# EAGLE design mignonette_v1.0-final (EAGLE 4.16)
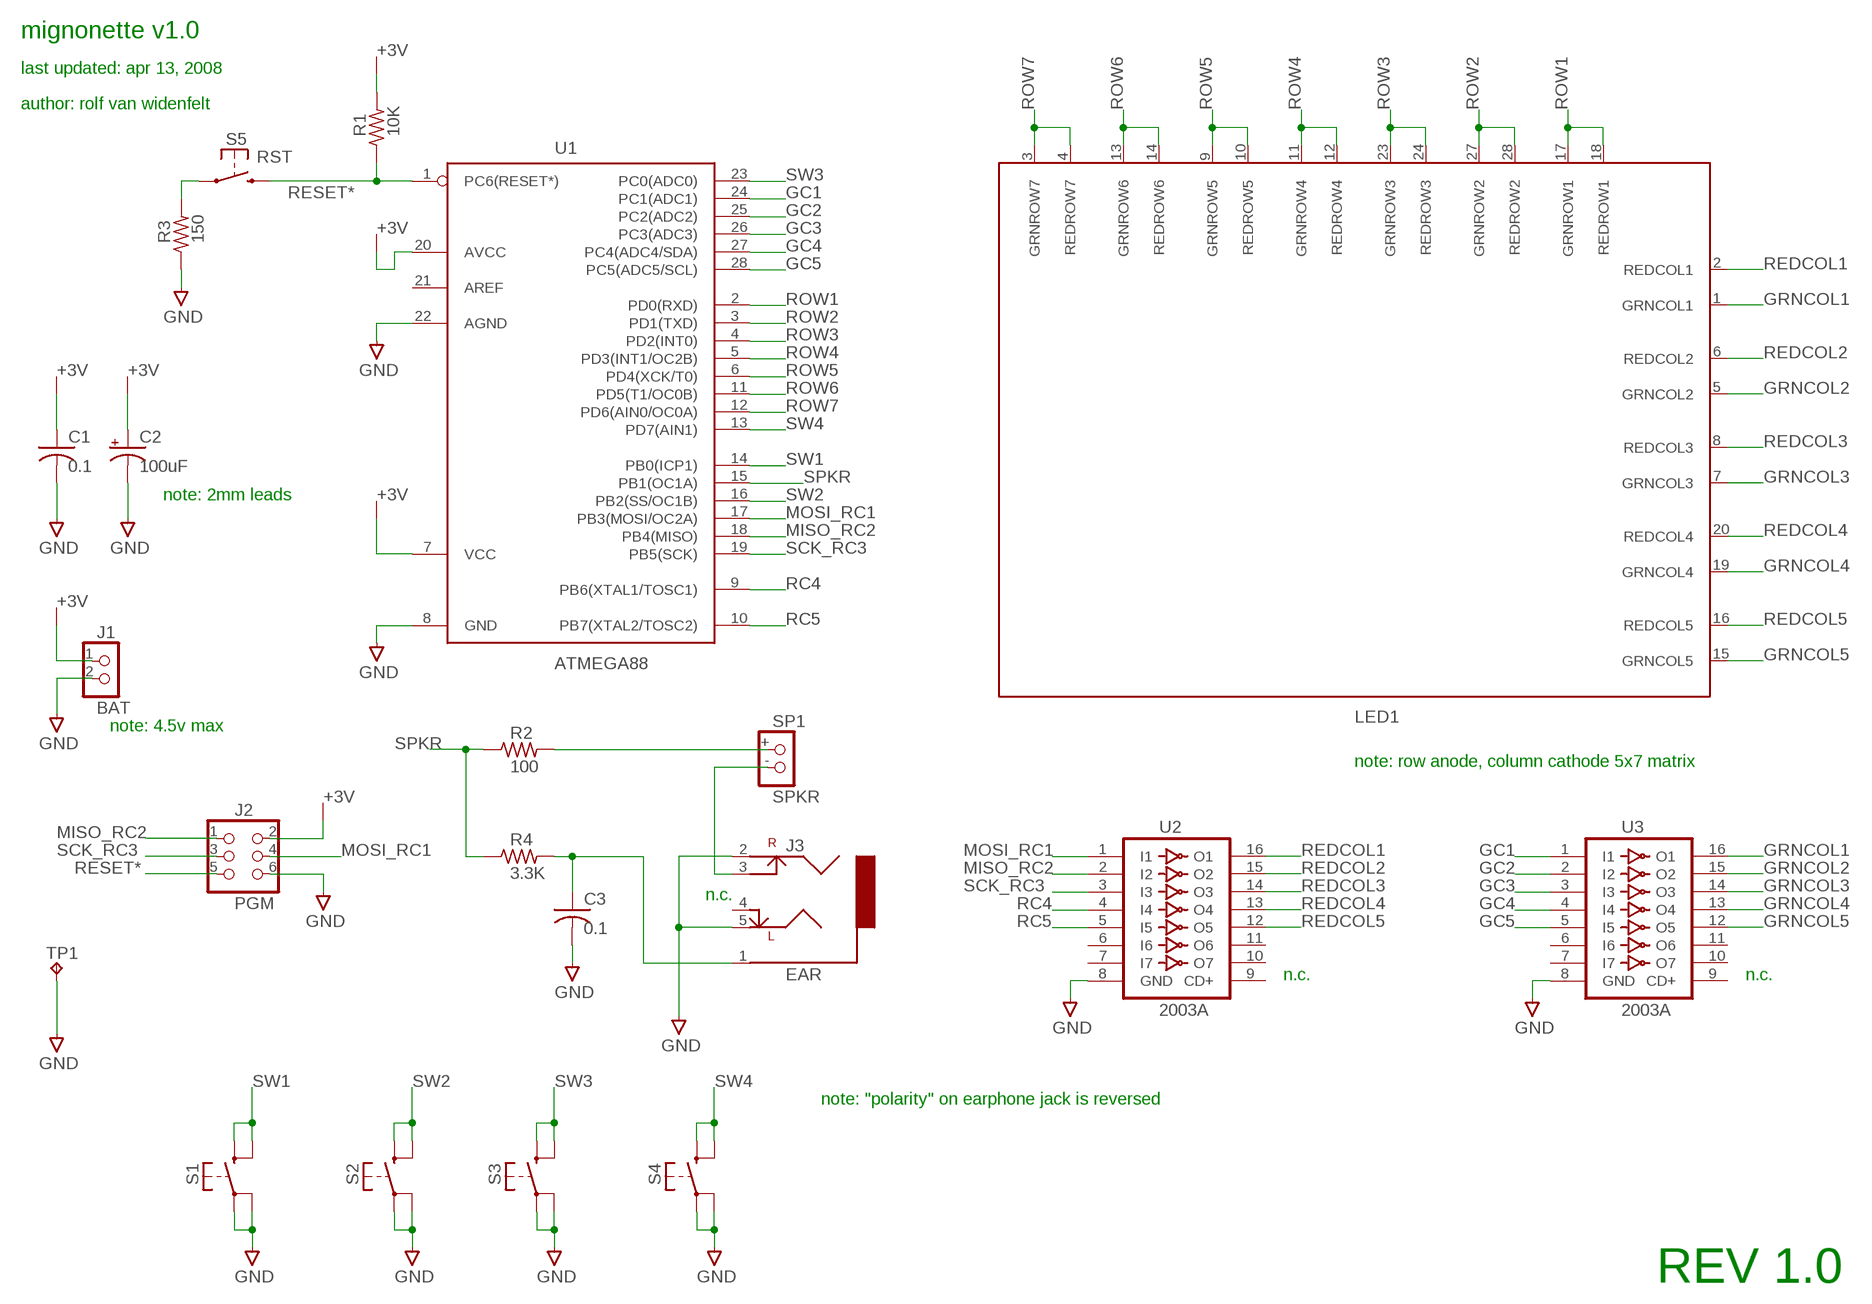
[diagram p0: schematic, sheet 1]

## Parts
C1  0.1  CAPACITORCAP100_FATPAD  [CAP100_FATPAD]
C2  100uF  CAPACITOR_POLPOLCAP2.0MM_FATPAD  [POLCAP2.0MM_FATPAD]
C3  0.1  CAPACITORCAP100_FATPAD  [CAP100_FATPAD]
J1  BAT  HEADER_1X2HEADER_1X2  [HEADER_1X2]
J2  PGM  HEADER_2X3HEADER_2X3  [HEADER_2X3]
J3  EAR  AUDIOJACK-SWITCHEDSTX-3081  [KYCON-STX-3081]
LED1  BICOLOR_5X7BICOLOR_28PIN  [BICOLOR_28PIN]
R1  10K  RESISTORRES350_FATPAD  [RES350_FATPAD]
R2  100  RESISTORRES350_FATPAD  [RES350_FATPAD]
R3  150  RESISTORRES350_FATPAD  [RES350_FATPAD]
R4  3.3K  RESISTORRES350_FATPAD  [RES350_FATPAD]
S1  TACTILE_SWITCH_SPSTB3F-1000-EASY  [B3F-1000-EASY]
S2  TACTILE_SWITCH_SPSTB3F-1000-EASY  [B3F-1000-EASY]
S3  TACTILE_SWITCH_SPSTB3F-1000-EASY-MIR  [B3F-1000-EASY-MIR]
S4  TACTILE_SWITCH_SPSTB3F-1000-EASY-MIR  [B3F-1000-EASY-MIR]
S5  RST  TACTILE_SPST  [TACTILE_SPST]
SP1  SPKR  BUZZERBUZZER_12MM  [BUZZER_12MM]
TP1  TESTPOINTTP_029  [TP_029]
U1  ATMEGA88  MEGAXX8DIL28-3  [DIL28-3]
U2  2003A  ULN2003AN  [DIL16]
U3  2003A  ULN2003AN  [DIL16]

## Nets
+3V: C1.1 C2.+ J1.1 J2.2 R1.2 U1.7(VCC) U1.20(AVCC)
EAROUT: C3.1 J3.1 R4.2
EARSW: J3.3 SP1.-
GC1: U1.24(PC1(ADC1)) U3.1(I1)
GC2: U1.25(PC2(ADC2)) U3.2(I2)
GC3: U1.26(PC3(ADC3)) U3.3(I3)
GC4: U1.27(PC4(ADC4/SDA)) U3.4(I4)
GC5: U1.28(PC5(ADC5/SCL)) U3.5(I5)
GND: C1.2 C2.- C3.2 J1.2 J2.6 J3.2 J3.5 R3.1 S1.P$1 S1.P$2 S2.P$1 S2.P$2 S3.P$1 S3.P$2 S4.P$1 S4.P$2 TP1.P$1(TP) U1.8(GND) U1.22(AGND) U2.8(GND) U3.8(GND)
GRNCOL1: LED1.1(GRNCOL1) U3.16(O1)
GRNCOL2: LED1.5(GRNCOL2) U3.15(O2)
GRNCOL3: LED1.7(GRNCOL3) U3.14(O3)
GRNCOL4: LED1.19(GRNCOL4) U3.13(O4)
GRNCOL5: LED1.15(GRNCOL5) U3.12(O5)
MISO_RC2: J2.1 U1.18(PB4(MISO)) U2.2(I2)
MOSI_RC1: J2.4 U1.17(PB3(MOSI/OC2A)) U2.1(I1)
N$2: R3.2 S5.P$1
N$3: R2.2 SP1.+
RC4: U1.9(PB6(XTAL1/TOSC1)) U2.4(I4)
RC5: U1.10(PB7(XTAL2/TOSC2)) U2.5(I5)
REDCOL1: LED1.2(REDCOL1) U2.16(O1)
REDCOL2: LED1.6(REDCOL2) U2.15(O2)
REDCOL3: LED1.8(REDCOL3) U2.14(O3)
REDCOL4: LED1.20(REDCOL4) U2.13(O4)
REDCOL5: LED1.16(REDCOL5) U2.12(O5)
RESET*: J2.5 R1.1 S5.P$2 U1.1(PC6(RESET*))
ROW1: LED1.17(GRNROW1) LED1.18(REDROW1) U1.2(PD0(RXD))
ROW2: LED1.27(GRNROW2) LED1.28(REDROW2) U1.3(PD1(TXD))
ROW3: LED1.23(GRNROW3) LED1.24(REDROW3) U1.4(PD2(INT0))
ROW4: LED1.11(GRNROW4) LED1.12(REDROW4) U1.5(PD3(INT1/OC2B))
ROW5: LED1.9(GRNROW5) LED1.10(REDROW5) U1.6(PD4(XCK/T0))
ROW6: LED1.13(GRNROW6) LED1.14(REDROW6) U1.11(PD5(T1/OC0B))
ROW7: LED1.3(GRNROW7) LED1.4(REDROW7) U1.12(PD6(AIN0/OC0A))
SCK_RC3: J2.3 U1.19(PB5(SCK)) U2.3(I3)
SPKR: R2.1 R4.1 U1.15(PB1(OC1A))
SW1: S1.P$3 S1.P$4 U1.14(PB0(ICP1))
SW2: S2.P$3 S2.P$4 U1.16(PB2(SS/OC1B))
SW3: S3.P$3 S3.P$4 U1.23(PC0(ADC0))
SW4: S4.P$3 S4.P$4 U1.13(PD7(AIN1))
Unconnected: J3.4 U1.21(AREF) U2.6(I6) U2.7(I7) U2.9(CD+) U2.10(O7) U2.11(O6) U3.6(I6) U3.7(I7) U3.9(CD+) U3.10(O7) U3.11(O6)

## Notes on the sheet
- mignonette v1.0
- last updated: apr 13, 2008
- author: rolf van widenfelt
- note: 2mm leads
- note: 4.5v max
- note: row anode, column cathode 5x7 matrix
- n.c.
- n.c. | n.c.
- note: "polarity" on earphone jack is reversed
- REV 1.0

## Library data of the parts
C1 C3 = basic:CAPACITOR
C2 = basic:CAPACITOR_POL
J1 = header-extras:HEADER_1X2
J2 = header-extras:HEADER_2X3
J3 = audiojack-kycon:AUDIOJACK-SWITCHED
LED1 = led5x7-bicolor:BICOLOR_5X7
R1-R4 = basic:RESISTOR: RESISTOR
S1-S4 = switch-omron-B3F:TACTILE_SWITCH_SPST
S5 = jameco-switches:TACTILE_SPST
SP1 = buzzer-pcmount:BUZZER
TP1 = testpoints:TESTPOINT
U1 = atmel-megaXX8-dip:MEGAXX8
U2 U3 = uln2003a:ULN2003A: DRIVER ARRAY

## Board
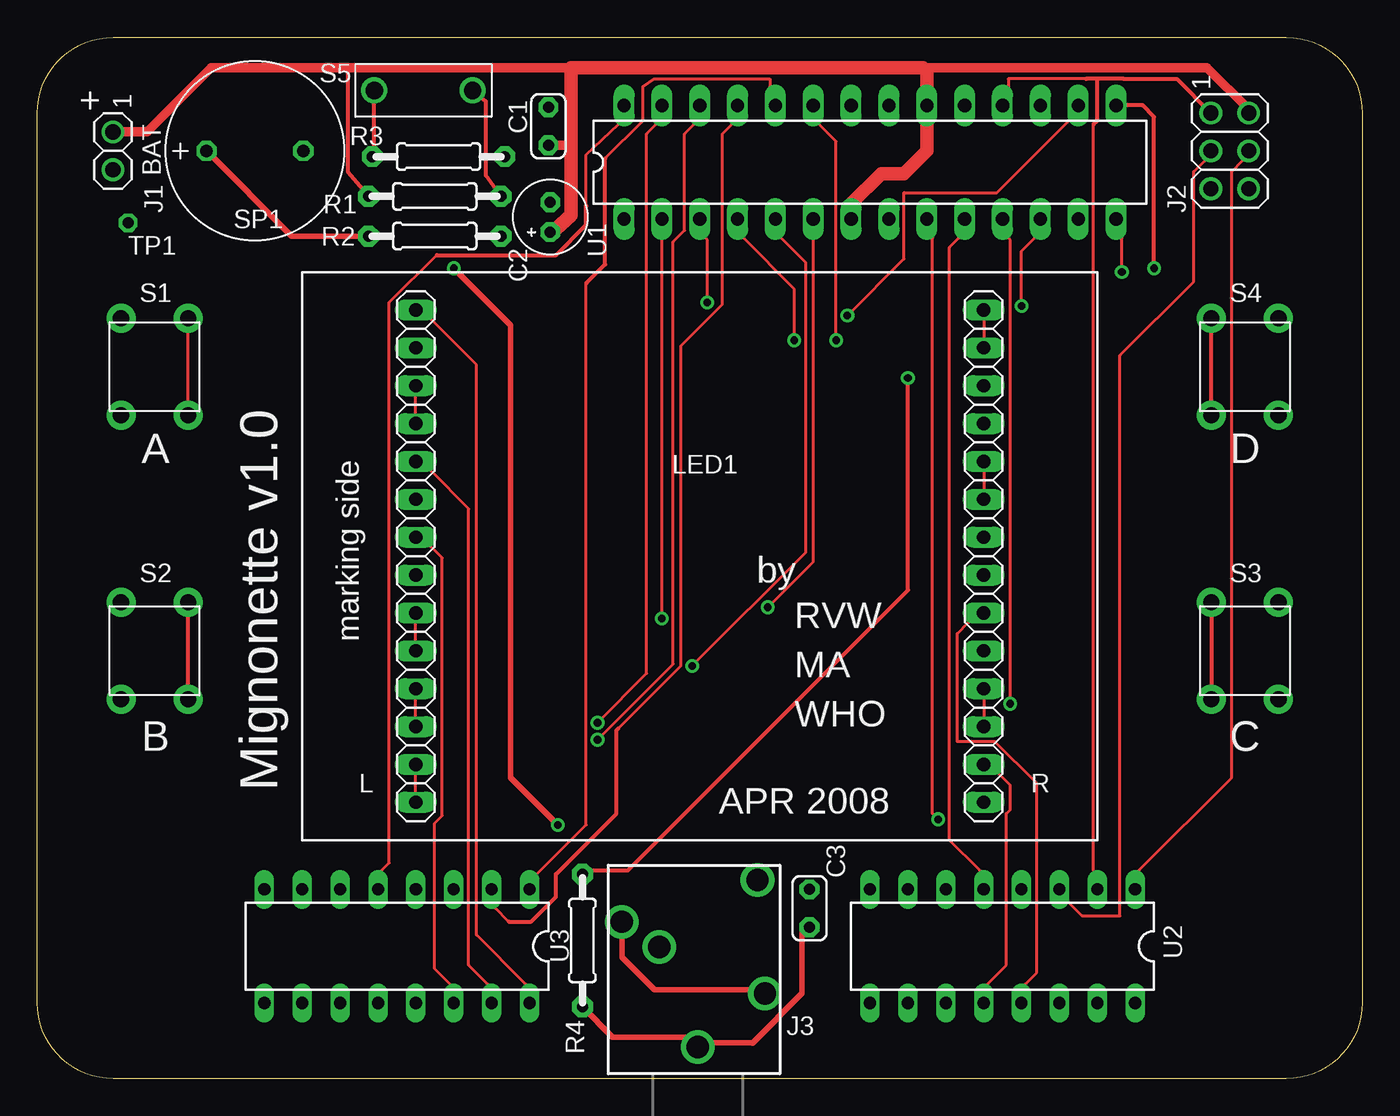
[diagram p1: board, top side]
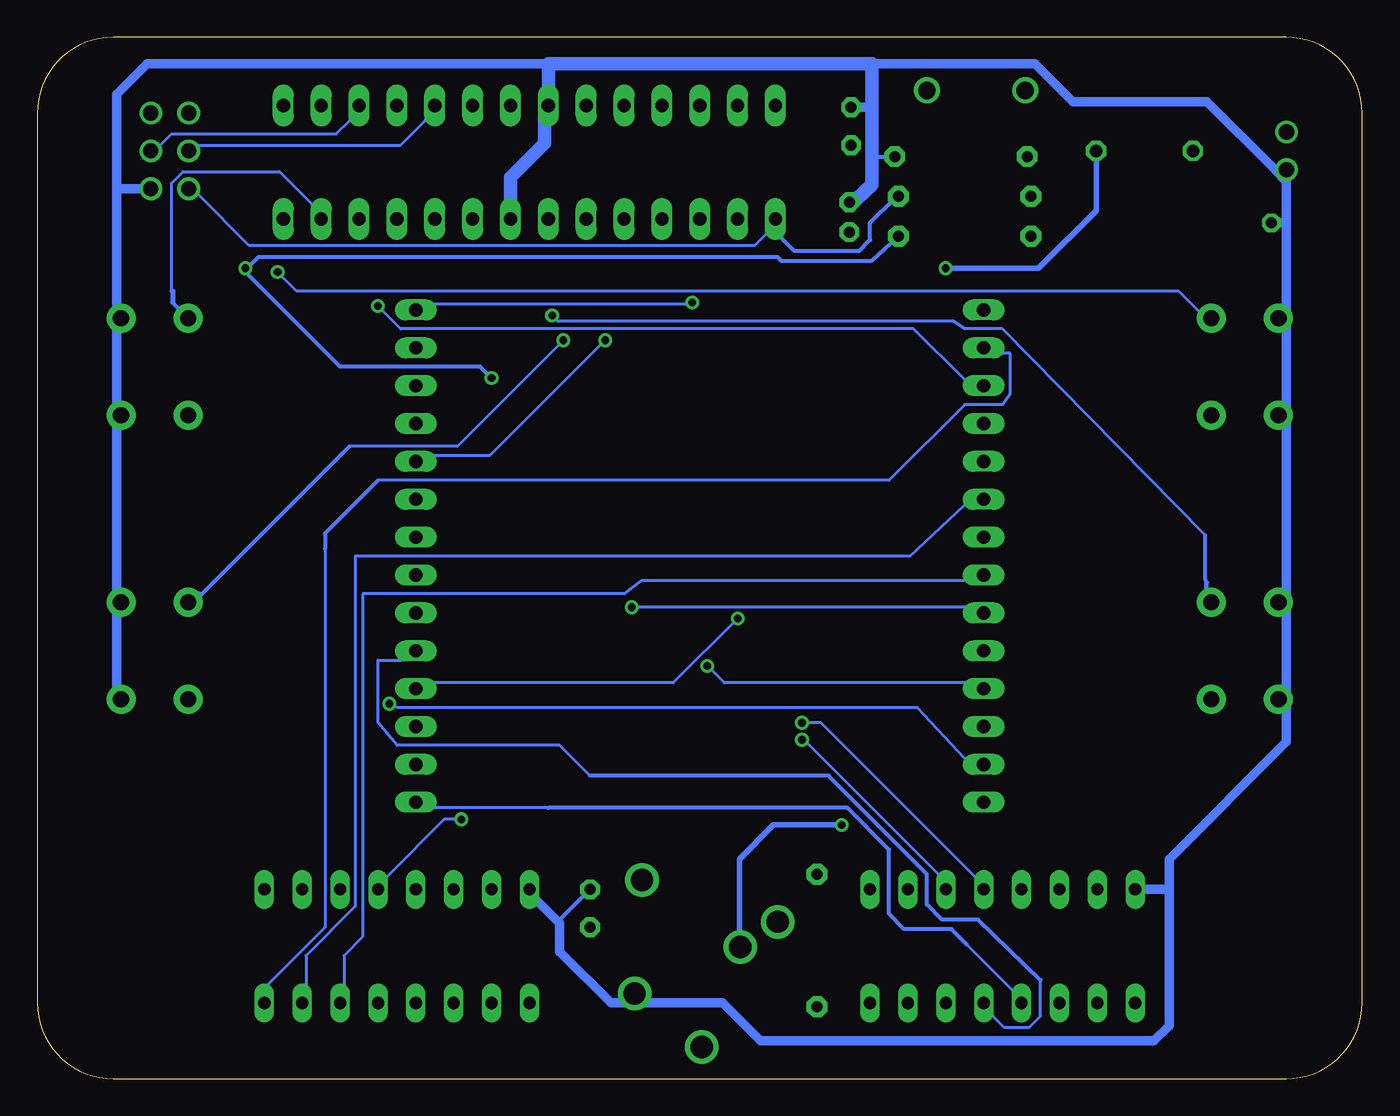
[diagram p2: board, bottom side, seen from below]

Size 88.9 x 69.85 mm. Coordinates in mm from the lower left corner, seen from the top.
Outline: 0,5.08 0,64.77 arc-90 5.08,69.85 83.82,69.85 arc-90 88.9,64.77 88.9,5.08 arc-90 83.82,0 5.08,0 arc-90 0,5.08
Copper layers (1*16): Top 0.035mm / dielectric 1.5mm / Bottom 0.035mm
Design rules "drc8mil10mil": minimum track width 8mil, minimum drill 20mil, track to track 8mil, track to pad 8mil, pad to pad 8mil, via to via 8mil, smd to smd 8mil, copper to edge 20mil, drill to drill 10mil, minimum pad ring 10mil, minimum via ring 8mil, stop-mask expansion 4mil, vias tented up to drill 0mil, thermal gap 10mil

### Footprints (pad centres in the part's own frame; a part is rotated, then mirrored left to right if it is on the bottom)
CAP100_FATPAD = drill 0.737 pad 1.321 octagon: 1 -1.27,0; 2 1.27,0
POLCAP2.0MM_FATPAD = drill 0.737 pad 1.321 octagon: + -1,0; - 1,0
HEADER_1X2 = drill 1.016 round: 1 -1.27,0; 2 1.27,0
HEADER_2X3 = drill 1.016 round: 1 -2.54,-1.27; 2 -2.54,1.27; 3 0,-1.27; 4 0,1.27; 5 2.54,-1.27; 6 2.54,1.27
KYCON-STX-3081 = drill 1.5 round: 1 -5.3,0; 2 -13.7,-5.1; 3 -12,-2.6; 4 -16.5,4; 5 -8.9,4.5
BICOLOR_28PIN = drill 0.889 long: 1 -19.05,16.51; 2 -19.05,13.97; 3 -19.05,11.43; 4 -19.05,8.89; 5 -19.05,6.35; 6 -19.05,3.81; 7 -19.05,1.27; 8 -19.05,-1.27; 9 -19.05,-3.81; 10 -19.05,-6.35; 11 -19.05,-8.89; 12 -19.05,-11.43; 13 -19.05,-13.97; 14 -19.05,-16.51; 15 19.05,-16.51; 16 19.05,-13.97; 17 19.05,-11.43; 18 19.05,-8.89; 19 19.05,-6.35; 20 19.05,-3.81; 21 19.05,-1.27; 22 19.05,1.27; 23 19.05,3.81; 24 19.05,6.35; 25 19.05,8.89; 26 19.05,11.43; 27 19.05,13.97; 28 19.05,16.51
RES350_FATPAD = drill 0.737 pad 1.397 octagon: 1 -4.445,0; 2 4.445,0
B3F-1000-EASY = drill 1.092 pad 1.93 round: P$1 -2.25,-3.25; P$2 -2.25,3.25; P$3 2.25,-3.25; P$4 2.25,3.25
B3F-1000-EASY-MIR = drill 1.092 pad 1.93 round: P$1 2.25,-3.25; P$2 2.25,3.25; P$3 -2.25,-3.25; P$4 -2.25,3.25
TACTILE_SPST = drill 1.168 round: P$1 0,0; P$2 0,6.604
BUZZER_12MM = drill 0.838 octagon: + -3.25,0; - 3.25,0
TP_029 = drill 0.737 octagon: P$1 0,0
DIL28-3 = drill 0.889 long: 1 -16.51,-3.81; 2 -13.97,-3.81; 3 -11.43,-3.81; 4 -8.89,-3.81; 5 -6.35,-3.81; 6 -3.81,-3.81; 7 -1.27,-3.81; 8 1.27,-3.81; 9 3.81,-3.81; 10 6.35,-3.81; 11 8.89,-3.81; 12 11.43,-3.81; 13 13.97,-3.81; 14 16.51,-3.81; 15 16.51,3.81; 16 13.97,3.81; 17 11.43,3.81; 18 8.89,3.81; 19 6.35,3.81; 20 3.81,3.81; 21 1.27,3.81; 22 -1.27,3.81; 23 -3.81,3.81; 24 -6.35,3.81; 25 -8.89,3.81; 26 -11.43,3.81; 27 -13.97,3.81; 28 -16.51,3.81
DIL16 = drill 0.813 long: 1 -8.89,-3.81; 2 -6.35,-3.81; 3 -3.81,-3.81; 4 -1.27,-3.81; 5 1.27,-3.81; 6 3.81,-3.81; 7 6.35,-3.81; 8 8.89,-3.81; 9 8.89,3.81; 10 6.35,3.81; 11 3.81,3.81; 12 1.27,3.81; 13 -1.27,3.81; 14 -3.81,3.81; 15 -6.35,3.81; 16 -8.89,3.81

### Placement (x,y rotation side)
C1  34.29,63.88 90 top
C2  34.42,57.78 90 top
C3  51.82,11.43 90 top
J1  5.08,62.23 270 top
J2  80.01,62.23 270 top
J3  44.32,-3.17 270 top
LED1  44.45,35.05 0 top
R1  26.67,59.18 180 top
R2  26.67,56.52 180 top
R3  26.92,61.85 180 top
R4  36.58,9.27 270 top
S1  7.87,47.75 0 top
S2  7.87,28.7 0 top
S3  81.03,28.7 0 top
S4  81.03,47.75 0 top
S5  22.61,66.29 270 top
SP1  14.61,62.23 0 top
TP1  6.1,57.4 0 top
U1  55.88,61.47 0 top
U2  64.77,8.89 180 top
U3  24.13,8.89 180 top

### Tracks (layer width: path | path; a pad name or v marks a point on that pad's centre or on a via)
+3V
  Top 0.254: R1.2 20.83,60.83 20.83,67.82
  Top 0.635: J2.2 81.28,65.02 78.49,67.82 59.44,67.82 59.69,67.56 | 35.81,67.82 20.83,67.82 11.68,67.82 7.37,63.5 J1.1 4.83,63.5 | 54.61,58.67 U1.7 | 34.42,56.64 C2.+ | 35.81,62.61 C1.1
  Top 0.889: 59.44,67.82 35.81,67.82 35.81,62.61 35.81,57.91 34.42,56.64 | 59.69,67.56 U1.20 59.69,62.23 58.17,60.71 56.64,60.71 54.61,58.67
EAROUT
  Top 0.254: 51.69,10.16 C3.1 | J3.1 44.32,2.16 44.32,2.41 | 47.94,2.41 47.97,2.38
  Top 0.381: R4.2 38.61,2.79 43.56,2.79 43.94,2.41 44.32,2.41 47.94,2.41 | 47.97,2.38 51.31,5.71 51.31,9.78 51.69,10.16
EARSW  (via drill 0.51)
  Top 0.381: v27.94,54.36 31.75,50.55 31.75,20.19 v34.92,17.02
  Bottom 0.254: 41.72,9.08 41.66,9.02 | J3.3 41.72,9.08 | 41.72,9.08 41.78,9.14
  Bottom 0.381: SP1.- 17.86,58.22 21.72,54.36 v27.94,54.36 | v34.92,17.02 39.5,17.02 41.78,14.73 41.78,9.14
GC1
  Top 0.203: 36.83,53.34 36.83,17.02 33.27,13.46 U3.1 | 38.1,61.72 40.64,64.26 40.64,66.55 41.4,67.06 49.15,67.06 49.15,66.55 U1.24
  Top 0.254: 38.1,61.72 38.1,54.61 36.83,53.34
GC2
  Top 0.203: 31.62,10.54 30.73,11.43 U3.2 | 38.99,23.5 43.18,27.69 43.18,49.15 45.97,51.94 45.97,63.37 46.61,64.01 U1.25
  Top 0.254: 31.62,10.54 33.15,10.54 34.8,12.19 34.8,13.72 38.86,17.78 38.86,23.37 38.99,23.5
GC3  (via drill 0.51)
  Top 0.203: v37.59,22.73 42.67,27.81 42.67,56.13 43.43,56.9 43.43,63.37 44.07,64.01 U1.26
  Bottom 0.203: v37.59,22.73 37.47,22.73 28.45,13.72 U3.3
GC4  (via drill 0.51)
  Top 0.203: v37.59,23.88 40.89,27.18 40.89,63.37 41.53,64.01 U1.27
  Bottom 0.203: v37.59,23.88 36.32,23.88 26.04,13.59 U3.4
GC5
  Top 0.203: 26.8,55.24 23.62,52.07 23.62,14.48 23.11,13.97 U3.5 | 36.83,58.55 36.83,61.98 38.99,64.01 U1.28
  Top 0.254: 36.83,58.55 36.83,57.28 34.8,55.24 26.8,55.24
GND
  Top 0.381: J3.2 39.22,8.15 41.4,5.97 48.9,5.97 48.88,5.98 J3.5
  Bottom 0.203: 83.57,43.69 83.69,43.69
  Bottom 0.254: C3.2 53.85,10.67 53.85,10.41 | 32.89,61.85 R3.1
  Bottom 0.381: 18.54,65.53 18.49,65.48
  Bottom 0.635: 5.84,60.96 J1.2 | 5.84,60.96 10.41,65.53 18.54,65.53 19.43,65.53 21.97,68.07 32.89,68.07 | 54.61,68.07 81.53,68.07 83.57,66.04 83.57,59.69 | 5.84,60.96 5.08,60.2 5.08,57.4 | 5.08,44.45 5.08,51.05 | 5.08,51.05 5.08,57.4 | 5.08,51.05 S1.P$2 | 5.08,44.45 S1.P$1 | 5.08,57.4 TP1.P$1 | 12.95,12.7 12.95,3.56 13.97,2.54 40.39,2.54 42.93,5.08 48.77,5.08 | 12.95,12.7 12.95,14.73 5.08,22.61 5.08,25.4 | U2.8 55.88,12.45 53.85,10.41 53.85,8.51 50.42,5.08 48.77,5.08 | 12.95,12.7 U3.8 | U1.22 54.86,65.02 | 83.57,59.69 J2.6 | 5.08,25.4 5.08,32 | 5.08,32 5.08,44.45 | S2.P$2 5.08,31.95 5.08,32 | S2.P$1 5.08,25.45 5.08,25.4 | 83.57,32 83.57,43.69 83.57,44.45 | 83.57,32 83.57,25.65 83.48,25.65 S3.P$1 | 83.57,59.69 83.57,51.05 | 83.57,51.05 83.57,44.45 | S4.P$2 83.33,51.05 83.57,51.05 | S4.P$1 83.33,44.45 83.57,44.45 | 83.57,32 83.31,32 83.31,31.99 S3.P$2 | 34.42,58.55 C2.- | 32.89,65.15 C1.2 | 48.77,5.08 48.77,5.33 48.82,5.39 J3.5
  Bottom 0.889: U1.8 57.15,60.45 54.86,62.74 54.86,65.02 | U1.22 54.61,68.07 32.89,68.07 32.89,65.15 32.89,61.85 32.89,59.94 34.42,58.55
GRNCOL1
  Top 0.203: U3.16 32.77,6.35 29.46,9.65 29.46,47.88 26.42,50.93 LED1.1
GRNCOL2
  Top 0.203: U3.15 30.23,6.35 28.96,7.62 28.96,38.23 26.42,40.77 LED1.5
GRNCOL3
  Top 0.203: U3.14 27.69,6.35 26.67,7.37 26.67,17.14 27.18,17.65 27.18,34.92 26.42,35.69 LED1.7
GRNCOL4
  Bottom 0.203: 21.59,6.6 21.59,4.19 22.35,3.43 24,3.43 24.77,4.19 U3.13 | 51.82,20.32 53.85,22.35 64.77,22.35 66.04,23.88 66.04,28.07 64.52,28.07 LED1.19
  Bottom 0.254: 21.59,6.6 25.78,10.67 28.19,10.67 29.21,11.68 29.21,13.72 35.81,20.32 51.82,20.32
GRNCOL5
  Bottom 0.203: 26.54,9.02 23.5,5.97 U3.12 | 54.61,18.16 62.23,18.16 LED1.15
  Bottom 0.254: 26.54,9.02 27.56,10.03 30.73,10.03 31.75,11.05 31.75,15.37 34.54,18.16 54.61,18.16
MISO_RC2
  Top 0.203: 70.87,64.01 70.87,13.97 U2.2 | 70.36,67.06 65.15,67.06 65.15,66.55 U1.18 | 70.48,67.06 71.12,67.06 72.9,67.06
  Top 0.254: J2.1 76.45,67.06 72.9,67.06 70.36,67.06 | 70.87,64.01 71.12,64.26 71.12,67.06
MOSI_RC1
  Top 0.203: U2.1 73.91,13.97 80.14,20.19 80.14,60.83 80.9,61.59 J2.4
  Bottom 0.203: U1.17 67.94,64.26 68.83,63.37 79.88,63.37 80.64,62.61 J2.4
N$2
  Top 0.254: R3.2 22.48,61.98 22.61,62.1 S5.P$1
N$3
  Top 0.381: SP1.+ 17.07,56.52 R2.2
RC4  (via drill 0.51)
  Top 0.203: v60.45,17.4 60.07,17.78 60.07,56.39 U1.9
  Bottom 0.203: v60.45,17.4 61.59,17.4 65.41,13.59 U2.4
RC5
  Top 0.203: U2.5 63.25,13.97 61.21,16 61.21,55.75 61.85,56.39 U1.10
REDCOL1
  Bottom 0.203: 69.6,35.56 69.6,10.16 73.41,6.35 U2.16 | 66.04,40.13 31.75,40.13 26.67,45.21 24.13,45.21 23.62,45.97 23.62,48.64 24.13,48.64 LED1.2
  Bottom 0.254: 66.04,40.13 69.6,36.58 69.6,35.56
REDCOL2
  Bottom 0.203: U2.15 70.87,6.35 70.87,8.26 67.56,11.56 67.56,35.05 30.35,35.05 26.67,38.48 LED1.6
REDCOL3
  Bottom 0.203: U2.14 68.33,6.35 68.33,8.26 67.06,9.53 67.06,32.51 49.53,32.51 48.39,33.4 26.67,33.4 LED1.8
REDCOL4
  Top 0.203: U2.13 66.29,6.35 67.06,7.11 67.06,19.81 64.26,22.61 61.72,22.61 61.72,29.84 62.48,30.61 LED1.20
REDCOL5
  Top 0.203: U2.12 63.75,6.35 65.02,7.62 65.02,17.78 65.28,18.03 65.28,19.68 64.52,20.45 LED1.16
RESET*
  Top 0.254: S5.P$2 30.1,65.53 30.1,60.58 R1.1
  Bottom 0.203: J2.5 78.11,59.31 74.68,55.88 40.77,55.88 40.01,56.64 U1.1
  Bottom 0.254: R1.1 31.37,59.05 33.02,57.4 33.02,56.26 33.78,55.5 38.1,55.5 39.37,56.77 U1.1
ROW1  (via drill 0.51)
  Top 0.203: LED1.18 LED1.17 | v41.91,30.86 U1.2
  Bottom 0.203: v41.91,30.86 46.23,26.54 62.23,26.54 LED1.18
ROW2  (via drill 0.51)
  Top 0.203: LED1.28 LED1.27 | v44.96,52.07 44.96,56.26 44.83,56.39 U1.3
  Bottom 0.203: v44.96,52.07 45.09,51.94 62.23,51.94 LED1.28
ROW3  (via drill 0.51)
  Top 0.203: LED1.24 LED1.23 | v50.8,49.53 50.8,52.96 47.37,56.39 U1.4
  Bottom 0.203: v50.8,49.53 58.55,41.78 62.23,41.78 LED1.24
ROW4  (via drill 0.51)
  Top 0.203: LED1.12 LED1.11 | v43.94,27.69 51.56,35.31 51.56,54.74 49.91,56.39 U1.5
  Bottom 0.203: v43.94,27.69 42.8,26.54 26.67,26.54 LED1.11
ROW5  (via drill 0.51)
  Top 0.203: LED1.10 LED1.9 | v49.02,31.62 52.07,34.67 U1.6
  Bottom 0.203: v49.02,31.62 26.67,31.62 LED1.9
ROW6  (via drill 0.51)
  Top 0.203: LED1.14 LED1.13 | v65.28,25.15 65.28,56.26 65.15,56.39 U1.11
  Bottom 0.203: v65.28,25.15 64.77,24.89 29.84,24.89 26.67,21.46 LED1.13
ROW7  (via drill 0.51)
  Top 0.203: LED1.4 LED1.3 | v66.04,51.82 66.04,55.5 66.93,56.39 U1.12
  Bottom 0.203: v66.04,51.82 64.52,50.29 30.1,50.29 26.67,46.86 LED1.3
SCK_RC3
  Top 0.203: U2.3 69.22,11.81 70.1,10.92 72.64,10.92 72.64,48.51 77.6,53.47 77.6,60.83 78.36,61.59 J2.3
  Bottom 0.203: U1.19 62.87,64.26 64.52,62.61 78.11,62.61 J2.3
SPKR  (via drill 0.51)
  Top 0.254: v58.42,46.99 58.42,32.77 39.62,13.97 36.83,13.97 R4.1 | v74.93,54.36 74.93,64.52 74.17,65.28 U1.15
  Bottom 0.254: v58.42,46.99 59.18,47.75 68.58,47.75 74.93,54.1 v74.93,54.36 | v74.93,54.36 75.06,54.36 | v74.93,54.36 74.8,54.36 74.04,55.12 39.24,55.12 38.99,54.86 32.89,54.86 R2.1
SW1  (via drill 0.51)
  Top 0.203: v72.77,54.1 72.77,56.39 U1.14 | S1.P$3 S1.P$4
  Bottom 0.203: v72.77,54.1 71.5,52.83 12.32,52.83 10.92,51.44 S1.P$4
SW2  (via drill 0.51)
  Top 0.203: v54.36,51.18 58.17,54.99 58.17,59.44 64.39,59.44 69.22,64.26 U1.16
  Top 0.254: S2.P$3 S2.P$4
  Bottom 0.203: v54.36,51.18 53.98,50.8 27.43,50.8 26.67,50.29 24.13,50.29 10.54,36.45 | 10.54,33.53 10.54,32.77
  Bottom 0.254: 10.54,36.45 10.54,33.53 10.41,33.27 10.41,32.24 S2.P$4
SW3  (via drill 0.51)
  Top 0.203: v53.59,49.53 53.59,62.87 52.45,64.01 U1.23
  Top 0.254: S3.P$4 S3.P$3
  Bottom 0.203: v53.59,49.53 60.71,42.42 67.94,42.42 | 77.92,32.45 77.98,32.38
  Bottom 0.254: 67.94,42.42 77.92,32.45 77.98,32.51 78.22,32.51 S3.P$4
SW4
  Top 0.254: S4.P$3 S4.P$4
  Bottom 0.203: 79.88,52.07 79.88,52.83 79.88,60.07 79.12,60.83 72.64,60.83 70.48,58.67 U1.13
  Bottom 0.254: 79.88,52.83 79.76,52.83 79.76,51.98 S4.P$4

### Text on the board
tPlace: + | A | D | by | RVW | MA | WHO | B | C | Mignonette v1.0 | APR 2008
